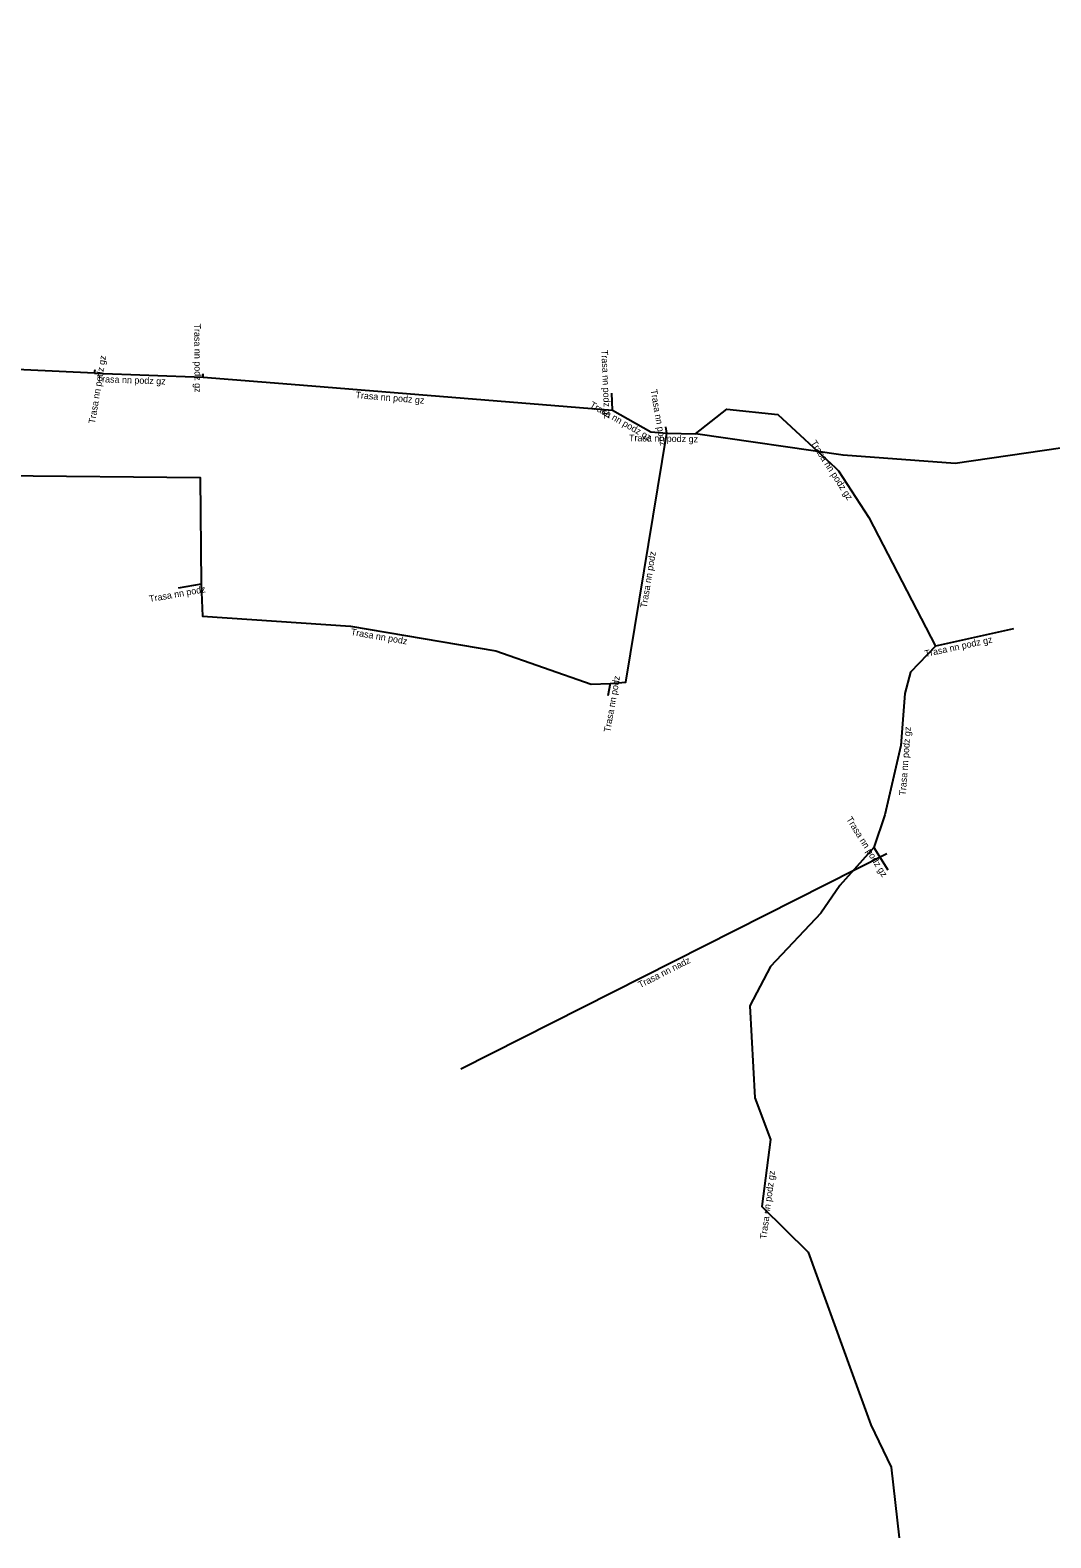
# Model space of a CAD drawing. Extents: x -778200 to -777730, y -1024936 to -1024518.
# Drawn here: x -777933.8 to -777857.4, y -1024935.7 to -1024822.9 of the extents above; entities that cross this region are included whole.
import ezdxf

# ---------------------------------------------------------------- set-up
doc = ezdxf.new("R2010")
doc.units = 0
doc.layers.add('Popiskový text - Ostatní atributy Trasy', color=7, linetype='Continuous')
doc.layers.add('Spojnice NN', color=7, linetype='Continuous')

msp = doc.modelspace()

# ---------------------------------------------------------------- linework, layer by layer
at = {"layer": 'Spojnice NN'}
for points in [[(-777729.91, -1024822.91), (-777764.36, -1024833.11), (-777784.9, -1024837.78), (-777822.56, -1024846.81), (-777853.99, -1024853.78), (-777864.6, -1024855.34), (-777872.99, -1024854.7), (-777884.05, -1024853.1)], [(-777929.02, -1024848.58), (-777951.24, -1024847.52), (-777951.5, -1024847.25)], [(-777929.02, -1024848.58), (-777928.97, -1024848.29)], [(-777929.02, -1024848.58), (-777920.88, -1024848.87)], [(-777920.88, -1024848.87), (-777920.88, -1024848.63)], [(-777920.88, -1024848.87), (-777914.29, -1024849.4), (-777890.24, -1024851.34)], [(-777890.24, -1024851.34), (-777890.3, -1024850.06)], [(-777890.24, -1024851.34), (-777887.38, -1024852.97), (-777886.19, -1024853.06)], [(-777884.05, -1024853.1), (-777881.7, -1024851.27), (-777877.89, -1024851.67), (-777873.57, -1024855.66), (-777873.33, -1024855.87), (-777871.07, -1024859.38), (-777866.09, -1024868.99)], [(-777886.19, -1024853.06), (-777886.27, -1024852.58)], [(-777890.43, -1024871.78), (-777889.25, -1024871.68), (-777886.19, -1024853.06)], [(-777886.19, -1024853.06), (-777884.05, -1024853.1)], [(-777966.11, -1024855.94), (-777921.11, -1024856.39), (-777921.03, -1024864.36)], [(-777921.03, -1024864.36), (-777922.76, -1024864.67)], [(-777921.03, -1024864.36), (-777920.93, -1024866.76), (-777909.86, -1024867.5), (-777898.98, -1024869.34), (-777891.85, -1024871.84), (-777890.43, -1024871.78)], [(-777860.25, -1024867.71), (-777866.09, -1024868.99)], [(-777866.09, -1024868.99), (-777867.94, -1024870.94), (-777868.38, -1024872.53), (-777868.68, -1024876.42), (-777869.86, -1024881.62), (-777870.69, -1024884.07)], [(-777890.43, -1024871.78), (-777890.59, -1024872.71)], [(-777870.69, -1024884.07), (-777873.25, -1024886.91), (-777874.65, -1024888.98), (-777878.42, -1024892.96), (-777879.97, -1024895.9), (-777879.59, -1024902.79), (-777878.43, -1024905.9), (-777879.07, -1024910.91), (-777875.6, -1024914.34), (-777872.38, -1024923.22), (-777870.91, -1024927.26), (-777869.41, -1024930.43), (-777868.8, -1024935.71)], [(-777870.69, -1024884.07), (-777869.65, -1024885.74)], [(-777869.72, -1024884.54), (-777901.61, -1024900.65)]]:
    msp.add_lwpolyline(points, dxfattribs=at)

# ---------------------------------------------------------------- texts
at = {"layer": 'Popiskový text - Ostatní atributy Trasy'}
for s, rotation, p in [('Trasa nn podz gz', 270.4677, (-777921.56, -1024844.86)), ('Trasa nn podz gz', 272.4973, (-777891.09, -1024846.84)), ('Trasa nn podz gz', 80.6316, (-777928.98, -1024852.38)), ('Trasa nn podz gz', 357.9651, (-777928.86, -1024849.24)), ('Trasa nn podz gz', 355.3918, (-777909.5, -1024850.44)), ('Trasa nn podz', 279.9051, (-777887.41, -1024849.83)), ('Trasa nn podz gz', 330.352, (-777892, -1024851.09)), ('Trasa nn podz gz', 359.0035, (-777889.02, -1024853.66)), ('Trasa nn podz gz', 302.8308, (-777875.45, -1024853.79)), ('Trasa nn podz', 80.6621, (-777887.69, -1024866.17)), ('Trasa nn podz', 10.1591, (-777924.88, -1024865.71)), ('Trasa nn podz', 350.3772, (-777909.86, -1024868.16)), ('Trasa nn podz gz', 12.3426, (-777866.83, -1024869.82)), ('Trasa nn podz', 79.9885, (-777890.42, -1024875.46)), ('Trasa nn podz gz', 85.6204, (-777868.31, -1024880.19)), ('Trasa nn podz gz', 301.8573, (-777872.78, -1024881.94)), ('Trasa nn nadz', 26.8103, (-777888.18, -1024894.59)), ('Trasa nn podz gz', 82.7245, (-777878.73, -1024913.39))]:
    msp.add_text(s, height=0.5, rotation=rotation, dxfattribs=at).set_placement(p)

doc.saveas('drawing.dxf')
